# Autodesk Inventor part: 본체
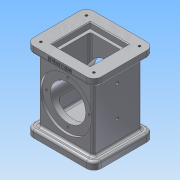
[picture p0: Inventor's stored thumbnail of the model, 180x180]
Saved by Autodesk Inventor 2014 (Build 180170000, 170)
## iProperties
Created: 2017-08
Part Number: 본체
Material: 알루미늄 6061
Document SubType Name: Modeling
Designer: oa51
Density: 2.71 g/cm^3
Appearance: 알루미늄 - 평지
Mass: 872.328 g
Surface Area: 642.254 cm^2
Volume: 321.892 cm^3
Author: oa51
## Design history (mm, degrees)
sketch "스케치1"
  geometry: L1 (-46, -41)-(46, -41); L2 (46, -41)-(46, 41); L3 (46, 41)-(-46, 41); L4 (-46, 41)-(-46, -41); L5 (-46, -41)-(46, 41); L6 (46, -41)-(-46, 41); 1 further point
  constraints: 12 end point, 2 midpoint, 2 parallel, 1 horizontal, 1 perpendicular
  dimensions: "d0" = 92 distance of L2.end L3.end; "d1" = 82 distance of L1.end L2.end
extrude "돌출1" new body sketch "스케치1" distance "d2" = 10; taper "d3" = 0 deg
node "작업 평면1"
sketch "스케치2"
  geometry: L1 (-37, -33)-(37, -33); L2 (37, -33)-(37, 33); L3 (37, 33)-(-37, 33); L4 (-37, 33)-(-37, -33); L5 (-37, -33)-(37, 33); L6 (37, -33)-(-37, 33); 1 further point
  constraints: 12 end point, 2 midpoint, 2 parallel, 1 horizontal, 1 perpendicular
  dimensions: "d5" = 74 distance of L2.end L3.end; "d6" = 66 distance of L1.end L2.end
extrude "돌출2" join sketch "스케치2" stored distance "d7" = 10; taper "d8" = 0 deg
sketch "스케치4"
  geometry: L1 (-33, 54)-(33, 54); L2 (-41, 0)-(41, 0) reference; L3 (-33, 98)-(33, 98) reference; L4 (-33, 10)-(-33, 98) reference; L5 (33, 10)-(-33, 10) reference; L6 (33, 10)-(33, 98) reference; L7 (-33, 54)-(-33, 89); L8 (-33, 89)-(-30, 89); L9 (-30, 89)-(-30, 78); L10 (-30, 78)-(30, 78); L11 (30, 78)-(30, 89); L12 (30, 89)-(33, 89); L13 (33, 54)-(33, 89); 1 further point
  constraints: 16 end point, 3 perpendicular, 2 midpoint, 2 parallel, 2 point on line, 1 collinear, 1 horizontal
  dimensions: "d12" = 108 diameter of L2 L1 (derived); "d13" = 3 distance of L7.end L8.end; "d14" = 3 distance of L11.end L12.end (= d13); "d15" = 70 diameter of L8 L1; "d16" = 70 diameter of L12 L1; "d17" = 48 diameter of L10 L1
revolve "회전1" sketch "스케치4" stored, may be unused: angle "d18" = 90 deg
sketch "스케치5"
  geometry: L1 (24, 19)-(68, 19); L2 (68, 19)-(68, 63); L3 (68, 63)-(24, 63); L4 (24, 63)-(24, 19); L5 (24, 19)-(68, 63); L6 (68, 19)-(24, 63); 1 further point
  constraints: 12 end point, 2 midpoint, 2 parallel, 1 horizontal, 1 perpendicular
  dimensions: "d19" = 44 distance of L2.end L3.end; "d20" = 44 distance of L1.end L2.end (= d19)
extrude "돌출3" cut sketch "스케치5" distance "d21" = 82; taper "d22" = 0 deg
sketch "스케치6"
  geometry: L1 (68, 63)-(68, 19) reference; L2 (68, 19)-(24, 19) reference; L3 (24, 19)-(24, 63) reference; L4 (24, 63)-(68, 63) reference; L5 (20, 15)-(72, 15); L6 (72, 15)-(72, 67); L7 (72, 67)-(20, 67); L8 (20, 67)-(20, 15); L9 (20, 15)-(72, 67); L10 (72, 15)-(20, 67); 1 further point
  constraints: 12 end point, 2 midpoint, 2 parallel, 1 horizontal, 1 perpendicular
  dimensions: "d23" = 52 distance of L6.end L7.end; "d24" = 52 distance of L5.end L6.end
extrude "돌출4" cut sketch "스케치6" distance "d25" = 8; taper "d26" = 0 deg
sketch "스케치7"
  geometry: L1 (-24, -24)-(24, -24); L2 (24, -24)-(24, 24); L3 (24, 24)-(-24, 24); L4 (-24, 24)-(-24, -24); L5 (-24, -24)-(24, 24); L6 (24, -24)-(-24, 24); 1 further point
  constraints: 12 end point, 2 midpoint, 2 parallel, 1 horizontal, 1 perpendicular
  dimensions: "d27" = 48 distance of L2.end L3.end; "d28" = 48 distance of L1.end L2.end (= d27)
extrude "돌출5" cut sketch "스케치7" distance "d29" = 16; taper "d30" = 0 deg
sketch "스케치8"
  geometry: L1 (0, 82)-(0, 0) reference; L2 (46, 41)-(36.381, 41); 4 further points
  constraints: 2 end point, 2 symmetric about line, 1 horizontal alignment, 1 perpendicular
  dimensions: "d31" = 72 distance of point (10, 72) point (82, 72); "d32" = 10 horizontal distance of L1.start point (10, 72); "d33" = 10 horizontal distance of L1.start point (10, 72)
hole "구멍1" sketch "스케치8" at (10, 72), (82, 72), (10, 10), (82, 10) diameter "d34" = 3.242; stored, may be unused: countersink angle "d38" = 90 deg, drill point angle "d40" = 118 deg; dims "d35" = 4, "d36" = 4, "d37" = 2, "d39" = 6
node "작업 평면2"
sketch "스케치9" dims "d41" = 58
  geometry: C1 r 35 at (0, 0) reference; C2 r 24 at (0, 0) reference; 6 further points
  constraints: 1 coincident, 1 vertical alignment, 7 other
  dimensions: "d44" = 360 deg dimension on C1.centre point (0, 29) (derived)
hole "구멍2" sketch "스케치9" at (0, 29), (-29, 0), (0, -29), (29, 0) diameter "d46" = 3.242; stored, may be unused: countersink angle "d50" = 90 deg, drill point angle "d52" = 118 deg; dims "d47" = 4, "d48" = 4, "d49" = 2, "d51" = 6
sketch "스케치10"
  geometry: L1 (-98, -8)-(-98, 74) reference; L2 (10, -8)-(10, 74) reference; 4 further points
  constraints: 2 horizontal alignment, 1 midpoint
  dimensions: "d53" = 38 distance from line of L2 point (-28, 33); "d54" = 42 distance of point (-70, 33) point (-28, 33)
hole "구멍3" sketch "스케치10" at (-70, 33), (-28, 33) diameter "d55" = 4.134; stored, may be unused: countersink angle "d59" = 90 deg, drill point angle "d61" = 118 deg; dims "d56" = 29, "d57" = 4, "d58" = 2, "d60" = 29
fillet "모깎기1" dims "d63" = 3
fillet "모깎기2" dims "d64" = 10
fillet "모깎기3" dims "d65" = 3
chamfer "모따기1" distance "d66" = 1; stored, may be unused: second distance "d67" = 2, angle "d68" = 45 deg
fillet "모깎기4" dims "d69" = 3
fillet "모깎기6" dims "d71" = 3
fillet "모깎기7" dims "d72" = 3
fillet "모깎기8" dims "d73" = 3
fillet "모깎기9" dims "d74" = 3
node "작업 평면3"
sketch "스케치11"
  geometry: L1 (0, 0)-(0, -7) reference; L2 (10, 0)-(82, 0) reference; 2 further points
  constraints: 1 other
  dimensions: "d75" = 46 distance from line of point (46, -4) L1; "d76" = 4 distance from line of L2 point (46, -4)
feature "엠보싱1" sketch "스케치11" dims "d0" = 92, "d1" = 82, "d77" = 0.5, "d78" = 0
node "솔리드1"
mirror "대칭1"
mirror "대칭2"
mirror "대칭3"
node "투영된 루프2"
other parameters: "d4" = -54, "d62" = 60.75
